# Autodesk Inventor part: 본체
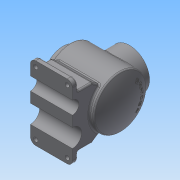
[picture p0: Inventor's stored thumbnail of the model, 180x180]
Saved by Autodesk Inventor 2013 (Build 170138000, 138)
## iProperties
Created: 2018-08
Part Number: 본체
Material: 일반
Document SubType Name: Modeling
Designer: Administrator
Density: 1 g/cm^3
Author: Administrator
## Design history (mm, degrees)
sketch "스케치1"
  geometry: L1 (0, 0)-(120, 0); L2 (0, 27)-(0, 38); L3 (0, 38)-(12, 38); L4 (12, 38)-(12, 50); L5 (12, 50)-(108.671, 50); L6 (0, 27)-(22, 27); L7 (22, 27)-(22, 40); L8 (22, 40)-(102.163, 40); A1 r 116 centre (4, 0) between (120, 0) and (108.671, 50); A2 r 106 centre (4, 0) between (110, 0) and (102.163, 40)
  constraints: 16 end point, 4 perpendicular, 4 point on circle, 3 parallel, 2 centre point, 2 point on line, 1 horizontal, 1 vertical alignment
  dimensions: "d1" = 54 diameter of L6 L1; "d2" = 100 diameter of L5 L1; "d3" = 76 diameter of L3 L1; "d5" = 22 distance of L2.start L6.end; "d7" = 116 radius of A1; "d8" = 10 radial gap between concentric circles of A1 A2; "d10" = 80 diameter of L8 L1; "d11" = 12 distance of L2.end L3.end; "d12" = 108 distance from line of L1.end L4
revolve "회전1" sketch "스케치1" stored, may be unused: angle "d13" = 90 deg
node "작업 평면1"
sketch "스케치2"
  geometry: L1 (-12, 50)-(-12, -50) reference; C1 r 38 at (-62, 0); 1 further point
  constraints: 1 centre point, 1 horizontal alignment
  dimensions: "d15" = 76 diameter of C1; "d17" = 50 distance from line of L1 C1.centre
extrude "돌출1" join sketch "스케치2" stored distance "d18" = 10; taper "d19" = 0 deg
sketch "스케치3"
  geometry: C1 r 27 at (0, 0); 1 further point
  constraints: 1 centre point
  dimensions: "d20" = 54 diameter of C1
extrude "돌출2" cut sketch "스케치3" stored distance "d21" = 10; taper "d22" = 0 deg
sketch "스케치4"
  geometry: 2 further points
  constraints: 1 vertical alignment
  dimensions: "d23" = 32.5 distance of point (0, 0) point (0, 32.5)
hole "구멍1" sketch "스케치4" at (0, 32.5) diameter "d24" = 3.242; stored, may be unused: countersink angle "d28" = 90 deg, drill point angle "d30" = 118 deg; dims "d25" = 8, "d26" = 4, "d27" = 2, "d29" = 10
sketch "스케치5"
  geometry: C1 r 27 at (0, 0) reference; 2 further points
  constraints: 1 vertical alignment
  dimensions: "d34" = 32.5 distance of C1.centre point (0, 32.5)
hole "구멍2" sketch "스케치5" at (0, 32.5) diameter "d35" = 3.242; stored, may be unused: countersink angle "d39" = 90 deg, drill point angle "d41" = 118 deg; dims "d36" = 8, "d37" = 4, "d38" = 2, "d40" = 10
node "작업 평면2"
sketch "스케치6"
  geometry: L1 (-20, -70)-(-100, -70); L2 (-100, -70)-(-100, 70); L3 (-100, 70)-(-20, 70); L4 (-20, 70)-(-20, -70); L5 (-20, -70)-(-100, 70); L6 (-100, -70)-(-20, 70); L7 (-12, 50)-(-12, -50) reference; 3 further points
  constraints: 12 end point, 3 midpoint, 2 parallel, 1 horizontal, 1 horizontal alignment, 1 perpendicular
  dimensions: "d46" = 80 distance of L2.end L3.end; "d47" = 140 distance of L1.end L2.end; "d48" = 8 distance between parallel lines of L4 L7
extrude "돌출3" join sketch "스케치6" distance "d49" = 10; taper "d50" = 0 deg
node "작업 평면3"
sketch "스케치7"
  geometry: L1 (32.558, 37.947)-(65, 37.947) reference; L2 (65, 37.947)-(65, 26.926) reference; L3 (65, 26.926)-(29.58, 26.926) reference; L4 (29.58, -26.926)-(65, -26.926) reference; L5 (65, -26.926)-(65, -37.947) reference; L6 (65, -37.947)-(32.558, -37.947) reference; L7 (-72, -70)-(-82, -70) reference; L8 (-82, -70)-(-82, 70) reference; L9 (-82, 70)-(-72, 70) reference; L10 (-72, 70)-(-72, -70) reference; L11 (-29.921, 40.059)-(-44.117, 50); L12 (-44.117, 50)-(-72, 50); L13 (-44.117, -50)-(-72, -50); L14 (-20.664, -33.578)-(-21.175, -33.936); L15 (-29.921, -40.059)-(-44.117, -50); L16 (-72, 50)-(-72, -50); A1 r 50 centre (0, 0) between (32.558, 37.947) and (32.558, -37.947) reference; A2 r 40 centre (0, 0) between (29.58, 26.926) and (29.58, -26.926) reference; A3 r 50 centre (0, 0) between (-29.921, 40.059) and (-29.921, -40.059); 1 further point
  constraints: 12 end point, 5 point on circle, 2 perpendicular, 2 point on line, 1 centre point, 1 collinear, 1 concentric
  dimensions: "d52" = 20 distance between parallel lines of L12 L9; "d53" = 20 distance between parallel lines of L7 L13; "d54" = 35 deg angle of L9 L11; "d56" = 35 deg angle of L7 L15
extrude "돌출4" join sketch "스케치7" stored distance "d57" = 80; taper "d58" = 0 deg
sketch "스케치8"
  geometry: L1 (0, 0)-(70, 0); L2 (70, 0)-(70, 18.804); C1 r 12.5 at (42.5, 0); C2 r 17.5 at (92.5, 0); 1 further point
  constraints: 4 end point, 2 centre point, 2 horizontal alignment, 1 horizontal, 1 perpendicular
  dimensions: "d59" = 12.5 radius of C1; "d60" = 17.5 radius of C2; "d61" = 27.5 distance of L1.end C1.centre; "d62" = 22.5 distance of C2.centre L1.end
extrude "돌출5" cut sketch "스케치8" stored distance "d63" = 80; taper "d64" = 0 deg
sketch "스케치9"
  geometry: L1 (20, 40)-(20, 70) reference; L2 (20, 70)-(100, 70) reference; L3 (100, 70)-(100, 40) reference; L4 (100, -70)-(20, -70) reference; 5 further points
  constraints: 2 horizontal alignment, 2 vertical alignment
  dimensions: "d65" = 10 distance from line of L1 point (30, 60); "d66" = 10 distance from line of point (30, 60) L2; "d67" = 10 distance from line of L3 point (90, 60); "d68" = 10 distance from line of L4 point (90, -60)
hole "구멍3" sketch "스케치9" at (30, -60), (90, -60), (90, 60), (30, 60) diameter "d69" = 8; stored, may be unused: countersink angle "d73" = 90 deg, drill point angle "d75" = 0 deg; dims "d70" = 8, "d71" = 4, "d72" = 2, "d74" = 10
node "작업 평면4"
sketch "스케치10"
  geometry: C1 r 32.5 at (0, 0); 1 further point
  constraints: 1 centre point, 1 coincident, 1 other
  dimensions: "d77" = 65 diameter of C1
feature "엠보싱1" sketch "스케치10" dims "d1" = 54, "d2" = 100, "d3" = 76, "d5" = 22, "d7" = 116, "d8" = 10, "d10" = 80, "d11" = 12, "d12" = 108, "d78" = 0.5, "d79" = 0
fillet "모깎기1" dims "d80" = 10, "d81" = 3
fillet "모깎기2" dims "d82" = 3
chamfer "모따기1" distance "d83" = 1; stored, may be unused: second distance "d84" = 2, angle "d85" = 45 deg
node "솔리드1"
pattern_circular "원형 패턴1" dims angle "d32" = 360 deg
pattern_circular "원형 패턴2" dims angle "d43" = 360 deg
node "절단 모서리 투영1"
other parameters: "d14" = 65, "d45" = -82, "d55" = 35 deg, "d76" = 128
